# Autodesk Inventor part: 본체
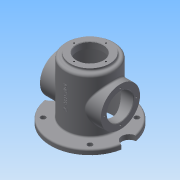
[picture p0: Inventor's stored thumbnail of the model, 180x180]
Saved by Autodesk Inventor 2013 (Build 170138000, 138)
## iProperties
Created: 2018-04
Part Number: 본체
Material: 일반
Document SubType Name: Modeling
Designer: Administrator
Density: 1 g/cm^3
Author: Administrator
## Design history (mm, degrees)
sketch "스케치1"
  geometry: C1 r 80 at (0, 0); 1 further point
  constraints: 1 centre point, 1 coincident
  dimensions: "d2" = 160 diameter of C1
extrude "돌출1" new body sketch "스케치1" distance "d4" = 10; taper "d5" = 0 deg
sketch "스케치2"
  geometry: C1 r 15 at (80, 0); C2 r 15 at (-80, 0); A1 r 80 centre (0, 0) between (80, 0) and (-80, 0) reference
  constraints: 2 centre point, 2 horizontal alignment, 2 point on circle, 1 equal radius
  dimensions: "d6" = 30 diameter of C1
extrude "돌출2" cut sketch "스케치2" distance "d8" = 10; taper "d9" = 0 deg
node "작업 평면1"
sketch "스케치3"
  geometry: L1 (0, 10)-(0, 125); L2 (0, 125)-(40, 125); L3 (78.594, 10)-(-78.594, 10) reference; L4 (40, 125)-(40, 120); L5 (40, 120)-(50, 120); L6 (50, 120)-(50, 10); 3 further points
  constraints: 10 end point, 4 midpoint, 4 perpendicular, 2 point on line, 1 vertical
  dimensions: "d19" = 100 diameter of L6 L1; "d21" = 80 diameter of L4 L1; "d23" = 5 distance of L2.end L4.end; "d30" = 110 distance between parallel lines of L3 L5
revolve "회전1" sketch "스케치3" stored, may be unused: angle "d24" = 90 deg
node "작업 평면2"
sketch "스케치4"
  geometry: L1 (-50, 120)-(50, 120) reference; L2 (14.934, 0)-(80, 0) reference; C1 r 40 at (0, 60); 2 further points
  constraints: 1 centre point, 1 midpoint, 1 vertical alignment
  dimensions: "d26" = 60 distance from line of L2 C1.centre; "d27" = 80 diameter of C1
extrude "돌출3" join sketch "스케치4" stored distance "d28" = 10; taper "d29" = 0 deg
sketch "스케치5" dims "d31" = 65
  geometry: C1 r 40 at (0, 0) reference; 3 further points
  constraints: 2 vertical alignment, 1 coincident, 2 other
hole "구멍1" sketch "스케치5" at (0, 32.5) diameter "d33" = 3.242; stored, may be unused: countersink angle "d37" = 90 deg, drill point angle "d39" = 118 deg; dims "d34" = 8, "d35" = 4, "d36" = 2, "d38" = 10
node "작업 평면3"
hole "구멍2" diameter "d46" = 54; stored, may be unused: countersink angle "d50" = 90 deg, drill point angle "d52" = 118 deg; dims "d44" = 10, "d45" = 10, "d47" = 8, "d48" = 4, "d49" = 2, "d51" = 10
node "작업 평면4"
sketch "스케치6"
  geometry: 1 further point
sketch "스케치7"
  geometry: L1 (0, 0)-(0, -8); L2 (-78.594, 0)-(78.594, 0) reference; L3 (0, -8)-(50, -8); L4 (50, -8)-(50, 0); 1 further point
  constraints: 6 end point, 1 midpoint, 1 parallel, 1 perpendicular, 1 point on line, 1 vertical
  dimensions: "d54" = 8 distance of L1.end L1.start; "d56" = 100 diameter of L4 L1
revolve "회전2" sketch "스케치7" stored, may be unused: angle "d57" = 90 deg
sketch "스케치8"
  geometry: L1 (-40, 125)-(40, 125) reference; L2 (-50, -8)-(50, -8) reference; L3 (0, 125)-(0, -8); L4 (27, 125)-(27, 112); L5 (27, 112)-(45, 112); L6 (45, 112)-(45, -8); L7 (27, 125)-(0, 125); L8 (0, -8)-(45, -8); 1 further point
  constraints: 12 end point, 2 midpoint, 2 perpendicular, 2 point on line, 1 collinear, 1 parallel
  dimensions: "d58" = 54 diameter of L4 L3; "d60" = 13 distance of L4.start L4.end; "d61" = 90 diameter of L6 L3
revolve "회전3" sketch "스케치8" stored, may be unused: angle "d62" = 90 deg
sketch "스케치9"
  geometry: L1 (0, 0)-(0, 67.5); L2 (0, 0)-(-47.73, 47.73); A1 r 80 centre (0, 0) between (78.594, 14.934) and (-78.594, 14.934) reference; A2 r 67.5 centre (0, 0) between (0, 67.5) and (-47.73, 47.73); 1 further point
  constraints: 4 end point, 2 coincident, 2 point on circle, 1 centre point, 1 vertical
  dimensions: "d63" = 135 diameter of A2; "d65" = 45 deg angle of L2 L1
hole "구멍3" sketch "스케치9" at (-47.73, 47.73) diameter "d67" = 10; stored, may be unused: countersink angle "d71" = 90 deg, drill point angle "d73" = 118 deg; dims "d68" = 8, "d69" = 4, "d70" = 2, "d72" = 10
node "작업 평면5"
sketch "스케치10" dims "d78" = 65
  geometry: C1 r 27 at (0, 0) reference; C2 r 40 at (0, 0) reference; 2 further points
  constraints: 2 vertical alignment, 1 coincident, 2 other
hole "구멍4" sketch "스케치10" at (0, 32.5) diameter "d81" = 3.242; stored, may be unused: countersink angle "d85" = 90 deg, drill point angle "d87" = 118 deg; dims "d82" = 8, "d83" = 4, "d84" = 2, "d86" = 10
fillet "모깎기1" dims "d91" = 3, "d92" = 5
fillet "모깎기2" dims "d93" = 3
chamfer "모따기1" distance "d94" = 1; stored, may be unused: second distance "d95" = 2, angle "d96" = 45 deg
fillet "모깎기3" dims "d97" = 3
chamfer "모따기2" distance "d98" = 1; stored, may be unused: second distance "d99" = 2, angle "d100" = 45 deg
node "작업 평면6"
sketch "스케치11"
  geometry: L1 (-78.594, 0)-(78.594, 0) reference; 3 further points
  constraints: 1 midpoint, 1 vertical alignment, 1 other
  dimensions: "d102" = 70 distance from line of L1 point (0, 70)
feature "엠보싱1" sketch "스케치11" dims "d103" = 0.5, "d104" = 0
node "솔리드1"
pattern_circular "원형 패턴1" dims angle "d41" = 360 deg
mirror "대칭1"
pattern_circular "원형 패턴2" dims angle "d75" = 360 deg
mirror "대칭2"
pattern_circular "원형 패턴3" dims angle "d89" = 360 deg
other parameters: "d10" = 0, "d25" = 62, "d43" = 0, "d53" = 0, "d77" = 0, "d101" = -83
